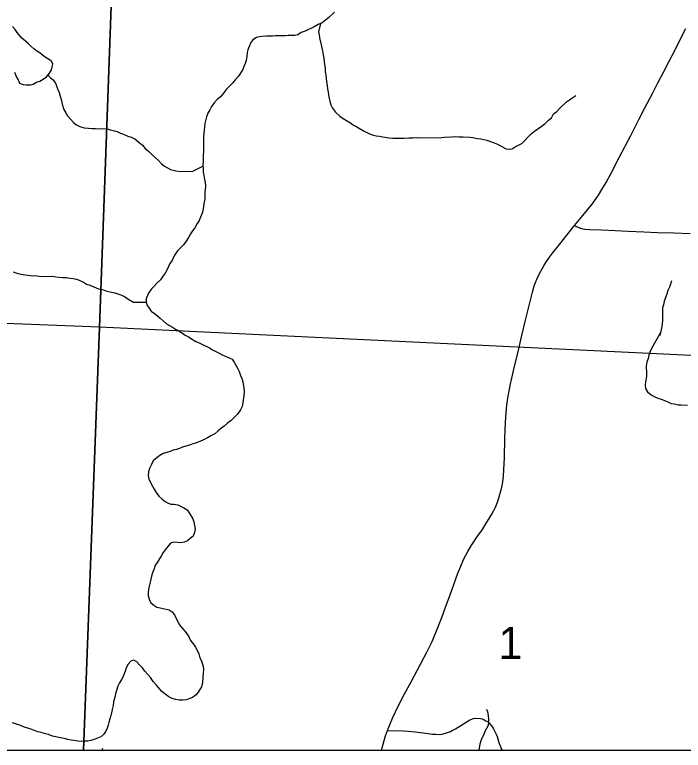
# Model space of a CAD drawing. Extents: x -3.3 to 34, y 0 to 56.8.
# Drawn here: x 0.477 to 1.347, y 28.077 to 29.034 of the extents above; entities that cross this region are included whole.
import ezdxf

# ---------------------------------------------------------------- set-up
doc = ezdxf.new("R2010")
doc.units = 0
for name, color, linetype in [('GM_X_Corporation', 7, 'Continuous'), ('GM_X_Section_Text', 7, 'Continuous'), ('GM_X_State_Route', 7, 'Continuous'), ('GM_X_Township_Road', 7, 'Continuous'), ('GT_Project_Soil_Layers', 7, 'Continuous'), ('SH_Data', 7, 'Continuous')]:
    doc.layers.add(name, color=color, linetype=linetype)

msp = doc.modelspace()

# ---------------------------------------------------------------- linework, layer by layer
at = {"layer": 'GM_X_Corporation'}
msp.add_lwpolyline([(-3.30393, 33.7379), (-3.30393, 28.07705), (1.56989, 28.07705), (1.59424, 28.73823), (1.64589, 29.81689), (1.65379, 30.0279), (1.68495, 30.79802), (1.68821, 30.98908), (1.68831, 30.9953), (1.68852, 31.00753), (1.69805, 31.56614), (1.74587, 32.36303)], dxfattribs=at)
for points in [[(0.62472, 29.64178), (0.58779, 28.6278), (-0.41373, 28.6668), (-0.38619, 29.67495)], [(1.6376, 29.60296), (1.63261, 29.48805), (1.59286, 28.57943), (0.58779, 28.6278), (0.62472, 29.64178)], [(-0.43836, 28.07705), (0.5667, 28.07705), (0.58779, 28.6278), (-0.41373, 28.6668)], [(0.5667, 28.07705), (1.57039, 28.07705), (1.58871, 28.4831), (1.59286, 28.57943), (0.58779, 28.6278)]]:
    msp.add_lwpolyline(points, close=True, dxfattribs=at)
at = {"layer": 'GM_X_State_Route'}
msp.add_lwpolyline([(0.95452, 28.07705), (0.95793, 28.08987), (0.95989, 28.09596), (0.96217, 28.10285), (0.96494, 28.10934), (0.96901, 28.11876), (0.97629, 28.13451), (0.98401, 28.14945), (0.99299, 28.16628), (1.01332, 28.20463), (1.02032, 28.21878), (1.02311, 28.22503), (1.02626, 28.23243), (1.03287, 28.24962), (1.03786, 28.26327), (1.04368, 28.2792), (1.04861, 28.2927), (1.05396, 28.30736), (1.05758, 28.31674), (1.06162, 28.32599), (1.06671, 28.33587), (1.07114, 28.34329), (1.07945, 28.35545), (1.08487, 28.36318), (1.09046, 28.37156), (1.09392, 28.37723), (1.09696, 28.382), (1.09983, 28.38734), (1.10271, 28.39343), (1.10526, 28.39992), (1.10764, 28.40674), (1.10994, 28.41447), (1.11118, 28.41957), (1.11233, 28.42631), (1.11332, 28.43387), (1.11381, 28.44209), (1.11439, 28.45787), (1.11487, 28.48316), (1.11573, 28.50358), (1.11614, 28.51002), (1.1167, 28.51674), (1.11772, 28.5261), (1.11893, 28.53508), (1.12007, 28.54209), (1.12186, 28.55163), (1.12397, 28.56111), (1.12776, 28.57699), (1.13217, 28.59543), (1.13685, 28.61499), (1.14161, 28.63493), (1.14619, 28.65409), (1.1508, 28.67333), (1.1533, 28.68136), (1.1549, 28.68561), (1.15716, 28.69103), (1.15933, 28.69574), (1.16167, 28.70039), (1.16598, 28.70807), (1.16913, 28.71295), (1.17307, 28.71887), (1.17702, 28.72404), (1.18598, 28.7353), (1.19569, 28.74743), (1.2058, 28.76005), (1.2164, 28.77309), (1.2284, 28.78783), (1.2367, 28.79942), (1.24131, 28.80666), (1.24689, 28.81586), (1.25331, 28.82786), (1.26391, 28.8485), (1.27869, 28.87703), (1.28938, 28.89766), (1.29678, 28.91205), (1.30693, 28.93176), (1.31391, 28.94531), (1.32046, 28.95786), (1.3283, 28.97273), (1.33748, 28.99013), (1.3458, 29.00712), (1.35022, 29.01611)], dxfattribs=at)
at = {"layer": 'GM_X_Township_Road'}
for points in [[(1.2058, 28.76005), (1.20998, 28.75783), (1.21145, 28.75708), (1.2128, 28.75647), (1.21384, 28.75619), (1.21479, 28.75598), (1.2189, 28.7553), (1.2257, 28.75484), (1.24083, 28.75417), (1.2584, 28.75339), (1.27528, 28.75257), (1.29574, 28.75156), (1.31375, 28.75089), (1.3347, 28.75012), (1.35599, 28.74933)], [(0.96217, 28.10285), (0.98307, 28.10216), (0.9891, 28.1018), (0.99848, 28.10097), (1.0087, 28.09967), (1.02084, 28.09818), (1.02478, 28.09785), (1.02931, 28.09777), (1.03314, 28.09817), (1.03776, 28.09921), (1.04059, 28.10009), (1.04446, 28.10164), (1.04659, 28.10272), (1.0507, 28.10511), (1.06804, 28.11594), (1.07084, 28.11725), (1.0742, 28.11826), (1.07712, 28.11871), (1.08284, 28.11851), (1.08563, 28.11788), (1.08808, 28.11687), (1.09041, 28.11559), (1.09227, 28.1143), (1.09515, 28.11177), (1.09876, 28.10735), (1.10024, 28.10516), (1.1025, 28.10083), (1.10378, 28.09791), (1.10483, 28.09507), (1.1075, 28.08598), (1.10872, 28.08296), (1.11078, 28.07851), (1.11153, 28.07705)]]:
    msp.add_lwpolyline(points, dxfattribs=at)
at = {"layer": 'GT_Project_Soil_Layers'}
msp.add_line((0.59132, 28.07705), (0.59214, 28.07989), dxfattribs=at)
for points in [[(0.89345, 29.03725), (0.88596, 29.03032), (0.88146, 29.02684), (0.87733, 29.02375), (0.87205, 29.0214), (0.86679, 29.01829), (0.86264, 29.01634), (0.85888, 29.01439), (0.85511, 29.01282), (0.8502, 29.01085), (0.84569, 29.00814), (0.84191, 29.00695), (0.83737, 29.00688), (0.83319, 29.00721), (0.82902, 29.00677), (0.81651, 29.0066), (0.81273, 29.00617), (0.80477, 29.00606), (0.79946, 29.0056), (0.79568, 29.00517), (0.7919, 29.00436), (0.787, 29.00164), (0.7844, 28.99781), (0.78219, 28.99285), (0.78073, 28.98865), (0.77965, 28.98485), (0.77933, 28.97991), (0.77827, 28.97458), (0.77718, 28.97077), (0.77534, 28.96657), (0.77426, 28.96277), (0.76831, 28.95396), (0.7642, 28.94935), (0.76084, 28.94513), (0.75299, 28.93705), (0.74888, 28.93207), (0.74516, 28.92708), (0.74066, 28.9236), (0.73692, 28.91938), (0.73319, 28.91478), (0.73135, 28.91058), (0.72876, 28.90599), (0.72693, 28.90141), (0.72584, 28.8976), (0.72477, 28.89265), (0.72407, 28.88809), (0.72375, 28.88391), (0.7231, 28.87593), (0.72316, 28.87176), (0.72284, 28.86721), (0.72299, 28.85545), (0.72267, 28.85165), (0.72235, 28.84671), (0.72241, 28.84254), (0.72208, 28.83874), (0.72253, 28.83343), (0.72259, 28.82926), (0.72341, 28.82472), (0.72423, 28.8198), (0.72505, 28.81563), (0.72549, 28.81109), (0.72484, 28.80311), (0.72452, 28.79855), (0.72458, 28.794), (0.72387, 28.7902), (0.72318, 28.78525), (0.72248, 28.78069), (0.72103, 28.77574), (0.7192, 28.77078), (0.71737, 28.76658), (0.71477, 28.76238)], [(0.47702, 28.95945), (0.47976, 28.95303), (0.48171, 28.94927), (0.48366, 28.94512), (0.48823, 28.94329), (0.49241, 28.94296), (0.49772, 28.94304), (0.5015, 28.94385), (0.50564, 28.94618), (0.51017, 28.94776), (0.51431, 28.9501), (0.51881, 28.95319), (0.52254, 28.95817), (0.52514, 28.96238), (0.52622, 28.96619), (0.52693, 28.97), (0.52536, 28.97377), (0.5158, 28.97971), (0.51043, 28.98419), (0.50623, 28.98679), (0.5024, 28.98977), (0.49818, 28.99313), (0.49509, 28.99688), (0.49126, 28.99986), (0.48666, 29.00359), (0.48049, 29.0111), (0.47779, 29.01485), (0.47432, 29.01898)], [(0.87524, 29.02282), (0.87256, 29.01192), (0.87337, 29.00776), (0.8738, 29.00397), (0.8762, 28.99489), (0.87782, 28.98733), (0.87865, 28.98203), (0.87947, 28.97749), (0.88033, 28.96953), (0.88116, 28.96461), (0.88123, 28.95968), (0.88204, 28.95589), (0.88292, 28.9468), (0.88374, 28.94188), (0.88418, 28.93771), (0.88499, 28.93355), (0.88542, 28.92976), (0.88624, 28.92522), (0.88743, 28.92144), (0.88863, 28.9169), (0.89058, 28.91238), (0.89482, 28.9075), (0.9002, 28.90227), (0.9048, 28.89891), (0.909, 28.89632), (0.91435, 28.89335), (0.91818, 28.89037), (0.92238, 28.88815), (0.93194, 28.88259), (0.93728, 28.88001), (0.94224, 28.8778), (0.94756, 28.87673), (0.95174, 28.87603), (0.9563, 28.87534), (0.96466, 28.87393), (0.96922, 28.87362), (0.97453, 28.87331), (0.98401, 28.87344), (0.99007, 28.8739), (0.99538, 28.87397), (0.99992, 28.87442), (1.00372, 28.87409), (1.03253, 28.87448), (1.0367, 28.87492), (1.0458, 28.87504), (1.05034, 28.87549), (1.05527, 28.87517), (1.06058, 28.87525), (1.06969, 28.87461), (1.07348, 28.87428), (1.07881, 28.87322), (1.08375, 28.87253), (1.08755, 28.87182), (1.09136, 28.87074), (1.10088, 28.86745), (1.10545, 28.86562), (1.10927, 28.86339), (1.11691, 28.8597), (1.12071, 28.859), (1.12449, 28.85981), (1.12863, 28.86214), (1.13691, 28.86643), (1.14926, 28.87912), (1.15376, 28.88259), (1.1624, 28.88878), (1.16728, 28.89264), (1.17177, 28.89688), (1.17552, 28.89996), (1.17848, 28.90532), (1.18261, 28.90841), (1.18672, 28.91264), (1.19533, 28.92072), (1.19909, 28.92343), (1.2036, 28.92653), (1.20736, 28.92886)], [(0.52067, 28.95587), (0.52376, 28.95212), (0.52758, 28.94952), (0.53069, 28.94425), (0.53305, 28.93783), (0.53501, 28.93293), (0.5366, 28.92801), (0.53819, 28.92235), (0.53901, 28.9178), (0.54138, 28.91063), (0.54409, 28.90649), (0.54604, 28.90272), (0.55027, 28.89785), (0.55374, 28.89372), (0.55757, 28.89074), (0.56215, 28.88853), (0.56786, 28.88709), (0.57318, 28.8864), (0.57811, 28.88609), (0.58228, 28.88615), (0.58646, 28.88582), (0.59176, 28.8859), (0.59708, 28.88559), (0.60203, 28.88414), (0.60697, 28.88307), (0.61077, 28.88236), (0.61497, 28.88014), (0.61878, 28.87868), (0.62451, 28.8761), (0.62908, 28.87465), (0.63366, 28.87243), (0.63941, 28.86796), (0.64363, 28.86422), (0.64709, 28.8601), (0.65169, 28.85636), (0.65631, 28.85188), (0.66014, 28.84851), (0.66437, 28.8444), (0.66822, 28.8399), (0.67243, 28.83692), (0.67626, 28.8347), (0.68007, 28.83285), (0.68711, 28.83101), (0.69341, 28.82996), (0.70916, 28.83066), (0.72222, 28.83709)], [(0.71477, 28.76238), (0.71181, 28.75702), (0.70845, 28.7528), (0.70623, 28.74898), (0.70363, 28.74439), (0.70029, 28.73941), (0.69694, 28.73481), (0.69245, 28.73058), (0.68908, 28.72674), (0.68574, 28.72176), (0.68351, 28.71793), (0.68205, 28.71412), (0.67907, 28.71028), (0.67722, 28.70646), (0.67539, 28.70189), (0.67316, 28.69806), (0.67056, 28.69423), (0.66684, 28.68925), (0.66272, 28.6854), (0.65936, 28.68118), (0.65562, 28.67771), (0.65189, 28.67273), (0.65005, 28.66891), (0.64859, 28.66434), (0.64826, 28.66054), (0.64945, 28.65676), (0.65217, 28.65224), (0.65487, 28.64849), (0.65908, 28.64551), (0.66292, 28.64214), (0.66676, 28.63916), (0.67059, 28.6358), (0.67481, 28.63207), (0.68246, 28.62762), (0.68666, 28.62502), (0.69086, 28.6228), (0.69545, 28.61983), (0.69928, 28.61722), (0.70348, 28.615), (0.70807, 28.61203), (0.71228, 28.60943), (0.71609, 28.60759)], [(0.47521, 28.69952), (0.48016, 28.69769), (0.48587, 28.69663), (0.49081, 28.69556), (0.49499, 28.69524), (0.49992, 28.69455), (0.50447, 28.69461), (0.50866, 28.69391), (0.51359, 28.6936), (0.52686, 28.69378), (0.53104, 28.69308), (0.53939, 28.69243), (0.5447, 28.69213), (0.54888, 28.69142), (0.55344, 28.69073), (0.55762, 28.69003), (0.56143, 28.68894), (0.56678, 28.68598), (0.5706, 28.68375), (0.57517, 28.6823), (0.58013, 28.68009), (0.58623, 28.67752), (0.59155, 28.67645), (0.59574, 28.67499), (0.59955, 28.67391), (0.60335, 28.6732), (0.60754, 28.67212), (0.61134, 28.67103), (0.61553, 28.66957), (0.62012, 28.66736), (0.62432, 28.66438), (0.63197, 28.65993), (0.64838, 28.66015)], [(1.33194, 28.68773), (1.33048, 28.68354), (1.32902, 28.67973), (1.32719, 28.67515), (1.32573, 28.67057), (1.32206, 28.66142), (1.32137, 28.65648), (1.32028, 28.65267), (1.31997, 28.64811), (1.32012, 28.63635), (1.3198, 28.63255), (1.31909, 28.62837), (1.31839, 28.62457), (1.31731, 28.62038), (1.3166, 28.61657)], [(1.31718, 28.61972), (1.30571, 28.59995), (1.30422, 28.59575), (1.30236, 28.59117), (1.30125, 28.58698), (1.29977, 28.58203), (1.29867, 28.57746), (1.29871, 28.57365), (1.29912, 28.56985), (1.29917, 28.56491), (1.29883, 28.56035), (1.2981, 28.55654), (1.29738, 28.55197), (1.2978, 28.54779), (1.30051, 28.54326), (1.30549, 28.5395), (1.30932, 28.53726), (1.31391, 28.5354), (1.31849, 28.53393), (1.32384, 28.5317), (1.32767, 28.52983), (1.33149, 28.52835), (1.33531, 28.52763), (1.34065, 28.52654), (1.34446, 28.52657), (1.35246, 28.52589)], [(0.71156, 28.60988), (0.73062, 28.60051), (0.73483, 28.59789), (0.74325, 28.59379), (0.74745, 28.59155), (0.75128, 28.58969), (0.75625, 28.58783), (0.76045, 28.58597), (0.76277, 28.5822), (0.7651, 28.57803), (0.7678, 28.5735), (0.76936, 28.56971), (0.77131, 28.56479), (0.77287, 28.56062), (0.77405, 28.55645), (0.77565, 28.5481), (0.77569, 28.5443), (0.77537, 28.53784), (0.77465, 28.53289), (0.7743, 28.52908), (0.7732, 28.52451), (0.77096, 28.51993), (0.7672, 28.51457), (0.76343, 28.51035), (0.75889, 28.50613), (0.75436, 28.50266), (0.74982, 28.49882), (0.74528, 28.49535), (0.7415, 28.49227), (0.73773, 28.48882), (0.73318, 28.48649), (0.72825, 28.4834), (0.72294, 28.48107), (0.71839, 28.47875), (0.7127, 28.47679), (0.7089, 28.47561), (0.70473, 28.47405), (0.70016, 28.47287), (0.69561, 28.4713), (0.69181, 28.46975), (0.68802, 28.46857), (0.68346, 28.46739), (0.67966, 28.46583), (0.6751, 28.46464), (0.67055, 28.46308), (0.666, 28.46075), (0.66222, 28.45768), (0.65768, 28.45383), (0.65507, 28.4481), (0.65282, 28.4439), (0.65134, 28.43933), (0.651, 28.43438), (0.65181, 28.42983), (0.65646, 28.42075), (0.65878, 28.41697), (0.66148, 28.41243), (0.66495, 28.4079), (0.6688, 28.40414), (0.67302, 28.40076), (0.67684, 28.39852), (0.68066, 28.39741), (0.68447, 28.39745), (0.68943, 28.39635), (0.69326, 28.39449), (0.69747, 28.39263), (0.70168, 28.39001), (0.70438, 28.38585), (0.70902, 28.3783), (0.7102, 28.37413), (0.71139, 28.36958), (0.71219, 28.36464), (0.71147, 28.36045), (0.70961, 28.35587), (0.70583, 28.35242), (0.70205, 28.34972), (0.69787, 28.34778), (0.69293, 28.34697), (0.68912, 28.34731), (0.68416, 28.34764), (0.67998, 28.34646), (0.67321, 28.33803), (0.67058, 28.33421), (0.66832, 28.33039), (0.66494, 28.32503), (0.66269, 28.32121), (0.65969, 28.317), (0.65858, 28.31318), (0.65709, 28.30937), (0.6556, 28.30517), (0.65488, 28.30136), (0.65341, 28.29565), (0.65231, 28.29069), (0.65159, 28.28613), (0.65086, 28.28232), (0.6509, 28.27852), (0.65208, 28.27359), (0.65441, 28.26905), (0.65825, 28.26566), (0.66208, 28.26342), (0.66666, 28.26232), (0.67047, 28.2616)], [(0.67047, 28.2616), (0.67429, 28.26088), (0.67849, 28.25978), (0.68232, 28.25715), (0.68579, 28.25224), (0.68735, 28.24846), (0.69162, 28.24013), (0.69584, 28.23561), (0.69855, 28.23184), (0.70162, 28.22807), (0.70433, 28.22391), (0.70627, 28.21975), (0.71012, 28.21522), (0.71244, 28.21106), (0.71476, 28.20728), (0.71671, 28.20274), (0.71828, 28.19743), (0.72022, 28.19365), (0.72257, 28.18607), (0.72299, 28.18227), (0.72231, 28.17276), (0.72163, 28.16439), (0.72015, 28.15943), (0.71677, 28.15408), (0.71339, 28.1491), (0.70885, 28.14564), (0.70505, 28.14446), (0.70088, 28.1429), (0.69593, 28.1421), (0.69136, 28.14243), (0.68678, 28.14315), (0.6822, 28.14424), (0.67799, 28.14648), (0.67262, 28.15061), (0.66879, 28.15362), (0.66186, 28.16192), (0.65763, 28.16644), (0.65415, 28.17173), (0.65069, 28.17549), (0.64646, 28.18001), (0.64375, 28.18417), (0.63991, 28.18832), (0.63607, 28.19208), (0.63224, 28.19432), (0.62844, 28.19315), (0.62505, 28.18931), (0.6228, 28.18511), (0.62169, 28.1813), (0.61983, 28.17672), (0.61834, 28.1729), (0.61609, 28.16908), (0.61384, 28.16487), (0.6116, 28.16029), (0.60974, 28.15495), (0.60864, 28.15038), (0.60754, 28.14619), (0.60607, 28.14009), (0.60535, 28.13552), (0.60426, 28.13019), (0.60315, 28.126), (0.60242, 28.12219), (0.60132, 28.118), (0.59984, 28.11342), (0.59911, 28.10961), (0.59762, 28.10579), (0.59575, 28.10197), (0.5935, 28.09815), (0.58934, 28.09469), (0.58517, 28.09275), (0.58062, 28.09118), (0.57644, 28.09), (0.57264, 28.08883), (0.56883, 28.08879), (0.56388, 28.08836), (0.55969, 28.08908), (0.55473, 28.08979), (0.55054, 28.09013), (0.54634, 28.09123), (0.54176, 28.09233), (0.5368, 28.09342), (0.53107, 28.09451), (0.52649, 28.0956), (0.52115, 28.09746), (0.51733, 28.09856), (0.51198, 28.10003), (0.5074, 28.10112), (0.5032, 28.1026), (0.49823, 28.10446), (0.48868, 28.10778), (0.48409, 28.10964), (0.47989, 28.11112), (0.47455, 28.11259)], [(1.09098, 28.13069), (1.09254, 28.1269), (1.09334, 28.12234), (1.09376, 28.11779), (1.0938, 28.11398), (1.09308, 28.10942), (1.09121, 28.1056), (1.08896, 28.10139), (1.08747, 28.09758), (1.0856, 28.09376), (1.08374, 28.08918), (1.08226, 28.08498), (1.08153, 28.08041), (1.08126, 28.07705)]]:
    msp.add_lwpolyline(points, dxfattribs=at)
at = {"layer": 'SH_Data'}
msp.add_line((-3.30393, 28.07705), (3.49607, 28.07705), dxfattribs=at)

# ---------------------------------------------------------------- texts
at = {"layer": 'GM_X_Section_Text'}
msp.add_text('1', height=0.04186, rotation=0.00001, dxfattribs=at).set_placement((1.1066, 28.19578))

doc.saveas('drawing.dxf')
